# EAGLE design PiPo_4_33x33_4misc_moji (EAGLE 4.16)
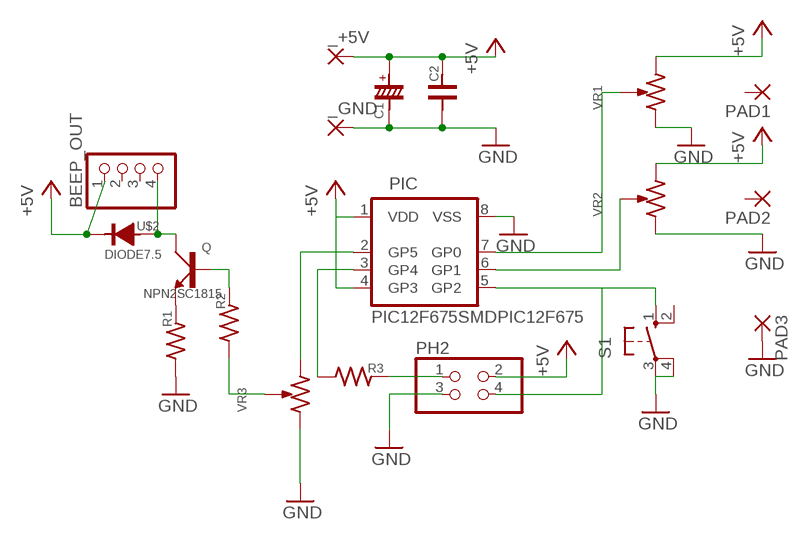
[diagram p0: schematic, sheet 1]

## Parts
_+5V  PAD2.5/0.9  [2,54/0,9]
_GND  PAD2.5/0.9  [2,54/0,9]
BEEP_OUT  PINHD-1X4  [1X04]
C1  POLCD5  [TT2D5]
C2  C0805  [R0805]
PAD1  PAD1.8/0.9  [1.80/0.9]
PAD2  PAD1.8/0.9  [1.80/0.9]
PAD3  PAD1.8/0.9  [1.80/0.9]
PH2  PINHD-2X2  [2X02]
PIC  PIC12F675SMDPIC12F675  [DIL08]
Q  NPN2SC1815  [TO92]
R1  RR_600MIL  [0204-15]
R2  RR_200MIL  [0204/5]
R3  RR_200MIL  [0204/5]
S1  10-XXSW1  [B3F-10XX]
U$2  DIODE7.5  [DIODE-D-7.5]
VR1  VRVR2  [VR2]
VR2  VRVR2  [VR2]
VR3  VRVR2  [VR2]

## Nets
+5V: _+5V.1(P) BEEP_OUT.1 C1.P$1 C2.2 PH2.2 PIC.1(VDD) PIC.4(GP3) U$2.P$1 VR1.P$3 VR2.P$3
GND: _GND.1(P) C1.P$2 C2.1 PAD3.1(P) PH2.3 PIC.8(VSS) R1.1 S1.3(P) S1.4(P1) VR1.P$1 VR2.P$1 VR3.P$1
N$1: PIC.6(GP1) VR2.P$2
N$2: PIC.7(GP0) VR1.P$2
N$3: PIC.2(GP5) VR3.P$3
N$5: PIC.3(GP4) R3.1
N$6: BEEP_OUT.4 Q.C U$2.P$2
N$8: PH2.1 R3.2
N$9: Q.E R1.2
N$10: R2.1 VR3.P$2
N$12: PH2.4 PIC.5(GP2) S1.1(S)
R2: Q.B R2.2
Unconnected: BEEP_OUT.2 BEEP_OUT.3 PAD1.1(P) PAD2.1(P) S1.2(S1)

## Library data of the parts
_+5V _GND PAD1-PAD3 = jikken:PAD: THROUGH-HOLE PAD
BEEP_OUT = pinhead:PINHD-1X4: PIN HEADER
C1 = jikken:POLC
C2 = jikken:C
PH2 = jikken:PINHD-2X2: PIN HEADER
PIC = jikken:PIC12F675SMD
Q = jikken:NPN
R1-R3 = jikken:R
S1 = jikken:10-XX: OMRON SWITCH
U$2 = jikken:DIODE
VR1-VR3 = jikken:VR

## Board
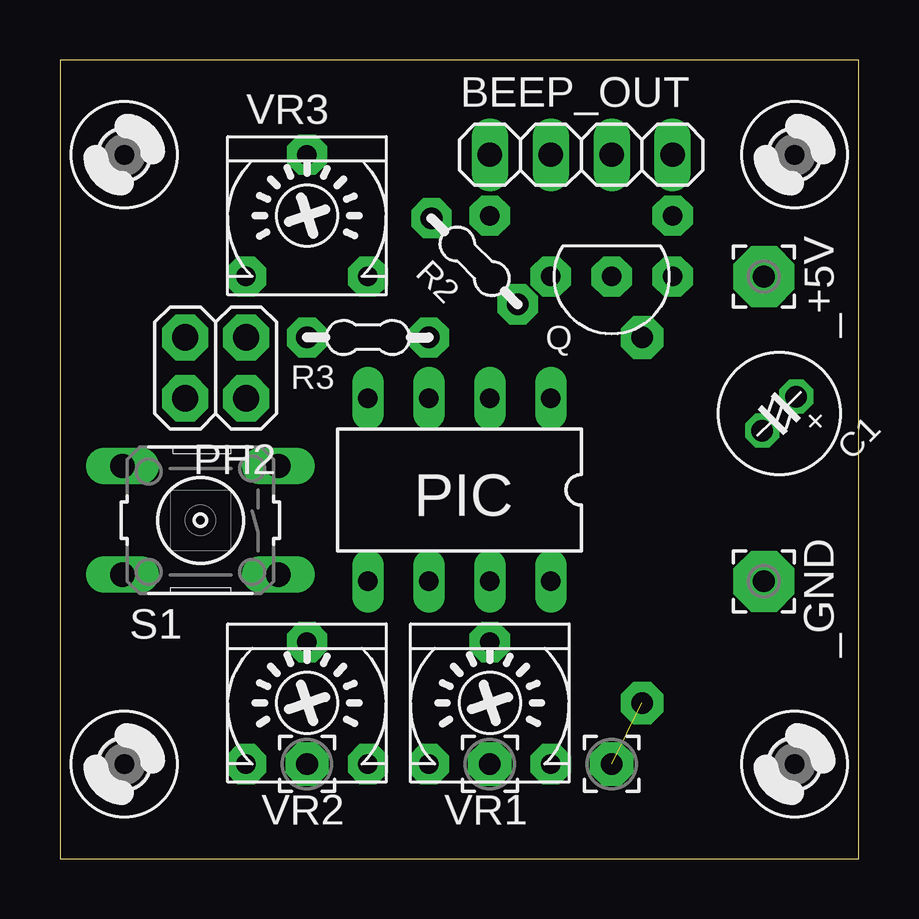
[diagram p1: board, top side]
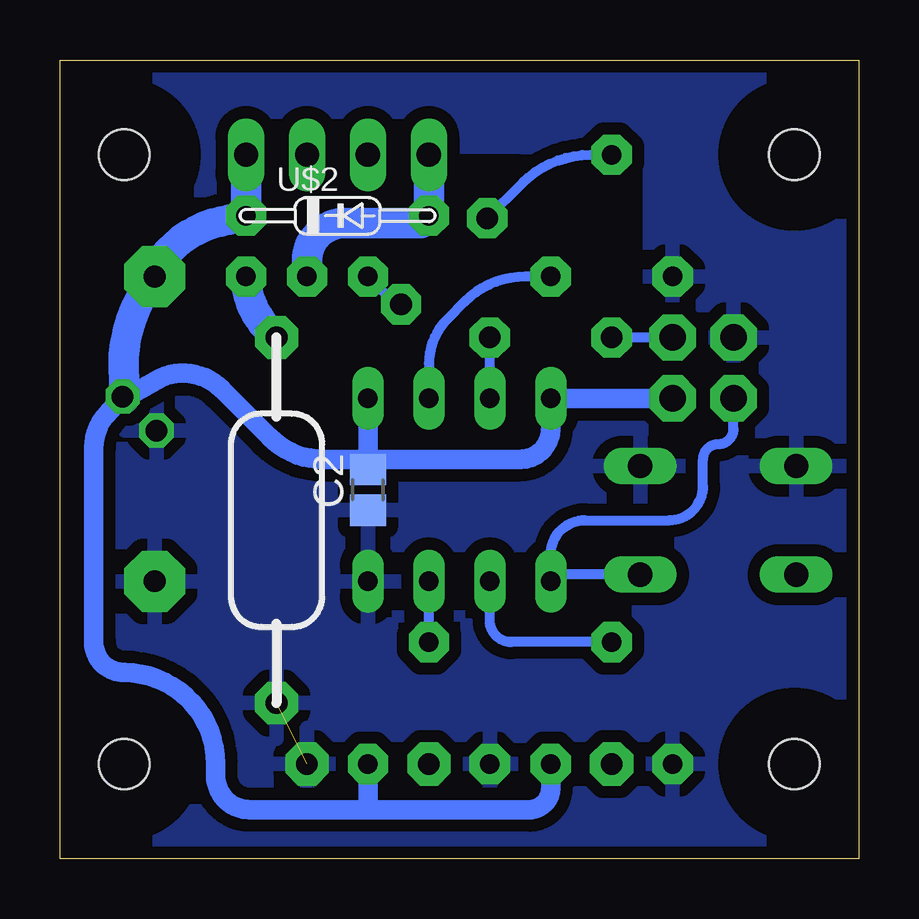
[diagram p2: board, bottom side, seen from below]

Size 33.3 x 33.3 mm. Coordinates in mm from the lower left corner, seen from the top.
Outline: 0,0 33.3,0 33.3,33.3 0,33.3 0,0
Copper layers (1*16): Top 0.035mm / dielectric 1.5mm / Bottom 0.035mm
Design rules "default": minimum track width 10mil, minimum drill 24mil, track to track 20mil, track to pad 20mil, pad to pad 20mil, via to via 20mil, smd to smd 8mil, copper to edge 20mil, drill to drill 8mil, minimum pad ring 10mil, minimum via ring 8mil, stop-mask expansion 4mil, vias tented up to drill 0mil, thermal gap 20mil
bRestrict: area 27.4,0.8 to 33.8,7.1; area -0.5,0.8 to 5.9,7.1; area -0.5,26.2 to 5.9,32.5; area 27.4,26.2 to 33.8,32.5; 2 lines

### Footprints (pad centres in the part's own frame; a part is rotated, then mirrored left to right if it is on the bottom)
2,54/0,9 = drill 0.914 pad 2.54 octagon: 1 0,0
1X04 = drill 1.016 long: 1 -3.81,0; 2 -1.27,0; 3 1.27,0; 4 3.81,0
TT2D5 = drill 0.9 pad 1.422 octagon: P$1 -1,0; P$2 1,0
R0805 = smd 1.3 x 1.5: 1 -0.85,0; 2 0.85,0
1.80/0.9 = drill 0.9 pad 1.8 octagon: 1 0,0
2X02 = drill 1.1 pad 1.93 octagon: 1 -1.27,-1.27; 2 -1.27,1.27; 3 1.27,-1.27; 4 1.27,1.27
DIL08 = drill 0.813 long: 1 -3.81,-3.81; 2 -1.27,-3.81; 3 1.27,-3.81; 4 3.81,-3.81; 5 3.81,3.81; 6 1.27,3.81; 7 -1.27,3.81; 8 -3.81,3.81
TO92 = drill 0.813 pad 1.676 octagon: B 2.54,0; C 0,0; E -2.54,0
0204-15 = drill 0.9 pad 1.778 octagon: 1 -7.62,0; 2 7.62,0
0204/5 = drill 0.9 pad 1.676 octagon: 1 -2.54,0; 2 2.54,0
B3F-10XX = drill 1.016 long: 1 -3.251,2.261; 2 3.251,2.261; 3 -3.251,-2.261; 4 3.251,-2.261
DIODE-D-7.5 = drill 0.813 pad 1.676 octagon: P$1 -3.81,0; P$2 3.81,0
2.1 = hole 2.1: 0,0
VR2 = drill 0.813 pad 1.676 octagon: P$1 -2.54,-2.54; P$2 0,2.54; P$3 2.54,-2.54

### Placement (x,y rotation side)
_+5V  29.35,24.27 90 top
_GND  29.35,11.57 90 top
BEEP_OUT  21.73,29.35 180 top
C1  29.98,18.55 225 top
C2  20.46,15.38 90 bottom
PAD1  17.92,3.95 0 top
PAD2  10.3,3.95 0 top
PAD3  23,3.95 0 top
PH2  6.49,20.46 180 top
PIC  16.65,15.38 180 top
Q  23,24.27 180 top
R1  24.27,14.11 90 bottom
R2  17.29,24.91 315 top
R3  12.84,21.73 180 top
S1  5.85,14.11 180 top
U$2  21.73,26.81 0 bottom
U$3  [2.1]  30.62,3.95 0 top
U$4  [2.1]  2.68,3.95 0 top
U$5  [2.1]  2.68,29.35 0 top
U$6  [2.1]  30.62,29.35 0 top
VR1  17.92,6.49 0 top
VR2  10.3,6.49 0 top
VR3  10.3,26.81 0 top

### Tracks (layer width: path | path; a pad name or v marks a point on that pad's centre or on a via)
+5V
  Bottom 0.406: 20.46,16.65 C2.2
  Bottom 0.813: 20.46,16.65 PIC.1 | 20.46,16.65 14.11,16.65 arc-90 12.84,17.92 PIC.4 PH2.2 | 20.46,16.65 22.32,16.65 arc45 24.57,17.58 26.56,19.58 arc-75 29.3,19.94 30.62,19.19 | VR2.P$3 12.84,2.94 arc90 13.74,2.04 20.46,2.04 | 20.46,2.04 VR1.P$3 | 20.46,2.04 25.39,2.04 arc90 26.81,3.46 26.81,3.95 arc-90 30.62,7.76 arc90 31.89,9.03 31.89,17.15 arc42 31.38,18.49 C1.P$1
  Bottom 1.27: BEEP_OUT.1 U$2.P$1 26.24,26.63 arc-54 29.42,24.42 _+5V.1 arc-45 30.62,19.93 30.62,19.19 C1.P$1
GND  (1 unrouted)
  pour Bottom: -1.77,35.7 -1.77,-1.13 34.43,-1.13 34.43,35.7
N$1
  Bottom 0.406: VR2.P$2 14.48,9.03 arc90 15.38,9.93 PIC.6
N$2
  Bottom 0.406: VR1.P$2 PIC.7
N$3
  Bottom 0.406: VR3.P$3 13.89,24.27 arc-45 16.43,23.22 17.15,22.5 arc-45 17.92,20.64 PIC.2
N$5
  Bottom 0.406: PIC.3 R3.1
N$6
  Bottom 1.27: BEEP_OUT.4 U$2.P$2 18.24,26.49 21.58,26.49 arc-90 23,24.75 Q.C
N$8
  Bottom 0.406: PH2.1 R3.2
N$9
  Bottom 1.27: Q.E arc-45 24.64,22.1 R1.2
N$10
  Bottom 0.406: R2.1 | R2.1 14.02,28.17 arc45 11.18,29.35 VR3.P$2
N$12
  Bottom 0.406: S1.1 12.84,11.85 PIC.5 12.84,12.69 arc90 11.42,14.11 7.91,14.11 arc-90 6.49,15.53 6.49,16.65 arc90 5.85,17.29 arc-90 5.22,17.92 PH2.4
R2
  Bottom 0.406: R2.2 19.3,23.11 Q.B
